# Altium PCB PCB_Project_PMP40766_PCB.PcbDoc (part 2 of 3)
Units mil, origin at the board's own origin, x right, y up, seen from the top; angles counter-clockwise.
Board outline 7480.31 x 3937.01 mil, 2 copper layers (Top Layer, Bottom Layer), stack 64.8 mil thick; 214 components, 118 nets, 518 pads, 70 vias.
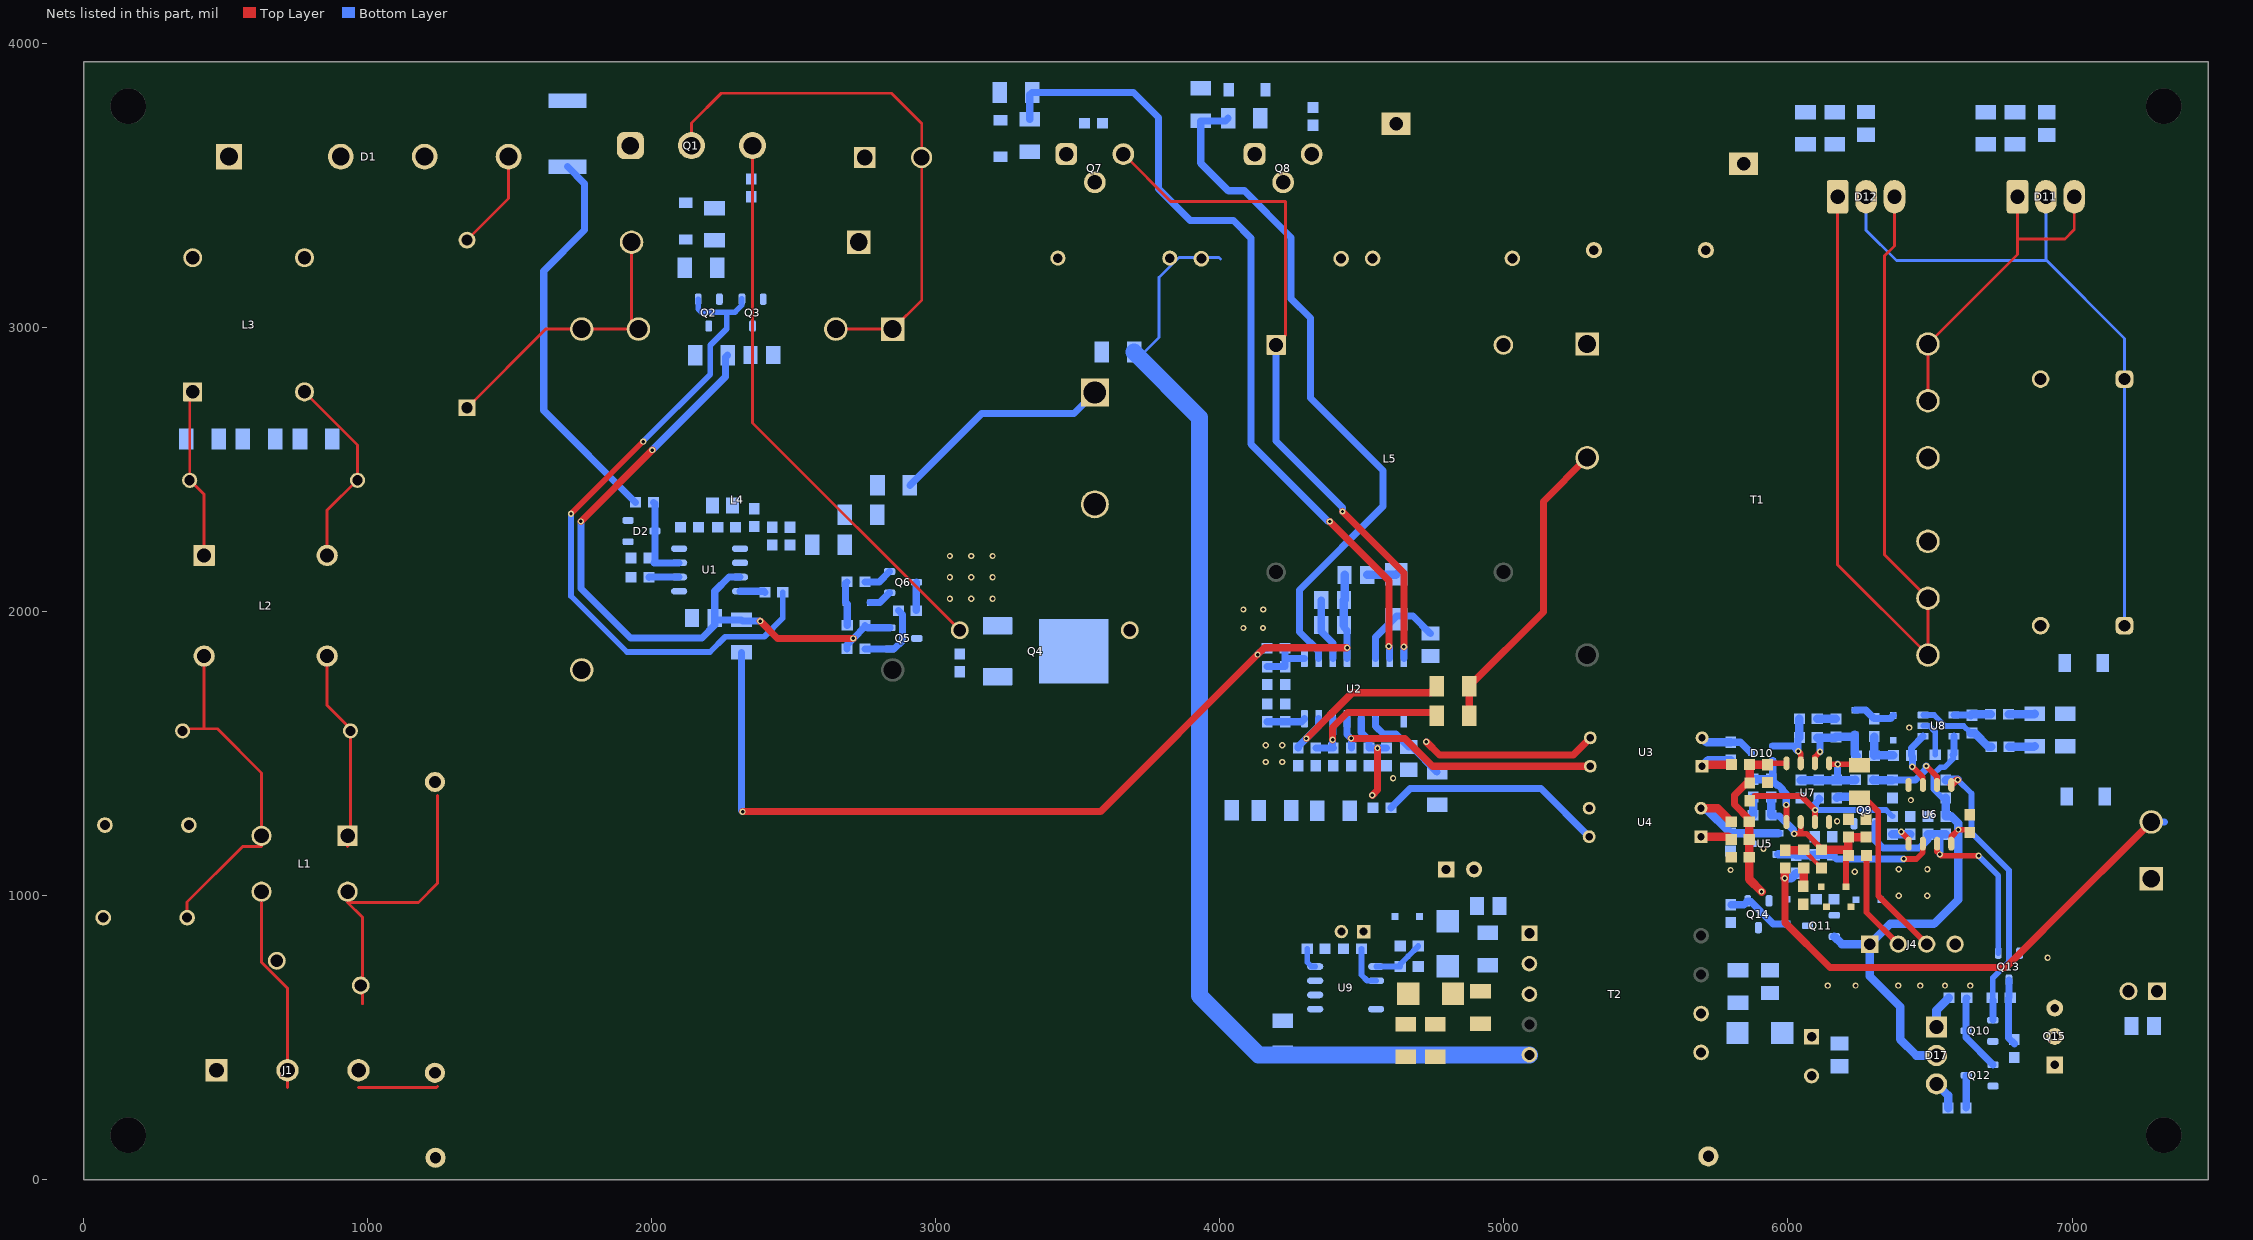
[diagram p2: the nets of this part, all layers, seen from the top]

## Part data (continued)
D13 D14 D15 D16: library part CMP-0028449-2, "Diode, Schottky, 30 V, 0.2 A, SOD-323", Manufacturer="Diodes Inc.", Value1=0.2A, Value2=1V
D17: library part CMP-0087778-1, "LED GRN/RED DIFF 5MM ROUND T/H", Color="Green, Red", Manufacturer="Marktech Optoelectronics"
D18: library part CMP-0085741-1, "Diode, Zener, 5.6 V, 300 mW, SOD-323", Manufacturer="ON Semiconductor", Power_W=300mW, Value1=0.3W
D19: library part CMP-0082069-2, "Diode, Switching, 75 V, 0.15 A, SOD-323", Manufacturer="Micro Commercial Components", Value1=0.15A, Value2=1V
D20 D22: library part CMP-0029024-2, "Diode, Ultrafast, 200 V, 1 A, SMA", Manufacturer="Diodes Inc.", Value1=1A, Value2=0.92V
D21: library part CMP-0076882-2, "Diode, Ultrafast, 1000 V, 1 A, SMA", Manufacturer="Diodes Inc.", Value1=1A, Value2=1.7V
D23: library part CMP-0085756-1, "Diode, Zener, 11 V, 300 mW, SOD-323", Manufacturer="ON Semiconductor", Power_W=300mW, Value1=0.3W
F1: library part CMP-0079917-2, "Fuse, 10 A, 250 VAC, TH", Irating_A=10A, Manufacturer=Littelfuse, PartNumber=0216008.MXEP, Supplier Part Number 1=F3603-ND
H1: library part 7106DG, Manufacturer=Aavid
H2: library part 7106DG, Manufacturer=Aavid, PartNumber=40mm*40mm
J1: library part CMP-0055483-1, "Terminal Block, 3x1, 6.35 mm, TH", Manufacturer="Phoenix Contact", Supplier Part Number 1=277-1270-ND
J2: library part CMP-0054770-2, "Receptacle, 5.08mm, 2x1, Brass, TH", Color=Green, Current_A=10A, Manufacturer="Wurth Elektronik", Supplier Part Number 1=732-2749-ND, Voltage_V=300V
J3: library part CMP-0055242-1, "Header(shrouded), 2.54mm, 2x1, Gold, TH", Color=Black, Current_A=3A, Manufacturer=Molex, Supplier Part Number 1=WM4800-ND, Voltage_V=250V
J4: library part CMP-0055331-1, "Header, 2.54mm, 4x1, Tin, TH", Color=Black, Current_A=4A, Manufacturer=Molex, Supplier Part Number 1=WM50016-04-ND, Voltage_V=250V
L1: library part CMP-0013095-2, "Coupled inductor, 8.5 A, 0.0055 ohm, TH", Manufacturer="Wurth Elektronik", Supplier Part Number 1=732-3246-ND
L2: library part CMP-0089807-1, "8.3mH @ 10kHz 2 Line Common Mode Choke Through Hole DCR 12mOhm", Manufacturer="Yaxing Development", Operating Temperature Range=to, Test Frequency=10kHz, Tolerance_%=30%
L3: library part CMP-0013082-2, "Coupled inductor, 7 mH, 7 A, 0.02 ohm, TH", Manufacturer="Wurth Elektronik", Supplier Part Number 1=732-5589-ND, ValueDisplayed=7mH
L4: library part "PFC Choke", "Transformer, 340 uH, TH", ValueDisplayed=340µH
L5: library part "LLC Inductor", "Transformer, 58uH, TH", ValueDisplayed=58µH
LOGO1: library part CMP-0074835-1, "IEC 61010-1 High Voltage Warning"
LOGO2: library part CMP-0074837-1, "IEC 61010-1 Hot Surface Warning"
Logo3: library part CMP-0074847-1, "FCC_disclaimer"
Logo4: library part CMP-0074769-1
Q1: library part CMP-0001178-3, "MOSFET, N-CH, 600 V, 37 A, TO-247", Alternate Manufacturer=None, Manufacturer="Infineon Technologies", Supplier Part Number 1=IPW60R080P7XKSA1-ND, Value2="51 nC"
Q2: library part CMP-0000461-2, "Transistor, NPN, 40 V, 0.6 A, SOT-23", Manufacturer="ON Semiconductor", Supplier Part Number 1=MMBT2222ALT1GOSCT-ND, Value1="0.6 A"
Q3: library part CMP-0000344-2, "Transistor, PNP, 60 V, 0.6 A, SOT-23", Manufacturer="ON Semiconductor", Supplier Part Number 1=MMBT2907ALT1GOSCT-ND, Value1="0.6 A"
Q4: library part CMP-0079238-2, "MOSFET, N-CH, 600 V, 18 A, DPAK", Alternate Manufacturer=None, Manufacturer="Infineon Technologies", Supplier Part Number 1=IPD60R180P7SAUMA1CT-ND, Value1="180m ohm", Value2="25 nC"
Q5: library part CMP-0000325-2, "Transistor, PNP, 40 V, 0.2 A, SOT-23", Manufacturer="ON Semiconductor", Supplier Part Number 1=MMBT3906LT1GOSCT-ND, Value1="0.2 A", Value2=300
Q6 Q11 Q14: library part CMP-0000419-2, "Transistor, NPN, 40 V, 0.2 A, SOT-23", Manufacturer="ON Semiconductor", Supplier Part Number 1=MMBT3904LT1GOSCT-ND, Value1="0.2 A", Value2=300
Q7 Q8: library part CMP-0079306-2, "MOSFET, N-CH, 600 V, 8 A, TO-220FP", Alternate Manufacturer=None, Manufacturer="Infineon Technologies", Value1="? ohm", Value2="28 nC"
Q9 Q10 Q12 Q13: library part CMP-0000769-1, "MOSFET, N-CH, 60 V, 0.17 A, SOT-23", Alternate Manufacturer=None, Manufacturer="Diodes Inc.", Supplier Part Number 1=2N7002-FDICT-ND, Value1=7, Value2="223 nC"
Q15: library part CMP-0000425-2, "Transistor, NPN, 40 V, 0.5 A, TO-92AP", Manufacturer="Micro Commercial Components", Supplier Part Number 1=2N4401-APCT-ND, Value1="0.5 A", Value2=300
R1 R2 R3: library part CMP-0018205-2, "RES, 330 k, 1%, 0.25 W, 1206", Manufacturer="Yageo America", Power_W=250mW, Supplier Part Number 1=311-330KFRCT-ND, TempCo="100 ppm/C", Tolerance_%=1%, Value2=0.25W, Value_Code=330k
R4 R18 R74: library part CMP-0018759-2, "RES, 0, 5%, 0.25 W, 1206", Manufacturer="Yageo America", Power_W=250mW, Supplier Part Number 1=311-0.0ERCT-ND, TempCo="200 ppm/C", Tolerance_%=5%, Value2=0.25W, Value_Code=0000, ValueDisplayed=0
R5: library part CMP-0022918-5, "RES, 220, 1%, 0.1 W, 0603", Manufacturer=Yageo, Power_W=100mW, Supplier Part Number 1=311-220HRCT-ND, TempCo="100 ppm/C", Tolerance_%=1%, Value2=0.1W, Value_Code=220R, ValueDisplayed=220
R6: library part CMP-0022913-5, "RES, 21.5 k, 1%, 0.1 W, 0603", Manufacturer=Yageo, Power_W=100mW, Supplier Part Number 1=311-21.5KHRCT-ND, TempCo="100 ppm/C", Tolerance_%=1%, Value2=0.1W, Value_Code=21k5, ValueDisplayed=21.5k
R7: library part CMP-0015773-2, "RES, 0.02, 1%, 2 W, 2512", Manufacturer="Stackpole Electronics Inc", Power_W=2W, Supplier Part Number 1=CSRN2512FK20L0CT-ND, TempCo="200 ppm/C", Tolerance_%=1%, Value_Code=R020, ValueDisplayed=0.02
R8 R20 R33 R34 R42 R44 R52 R84 R86: library part CMP-0022746-5, "RES, 10.0 k, 1%, 0.1 W, 0603", Manufacturer=Yageo, Power_W=100mW, Supplier Part Number 1=311-10.0KHRCT-ND, TempCo="100 ppm/C", Tolerance_%=1%, Value2=0.1W, Value_Code=10k0, ValueDisplayed=10.0k
R9 R12 R13: library part CMP-0018270-2, "RES, 3.30, 1%, 0.25 W, 1206", Manufacturer="Yageo America", Power_W=250mW, Supplier Part Number 1=311-3.30FRCT-ND, TempCo="200 ppm/C", Tolerance_%=1%, Value2=0.25W, Value_Code=3R30, ValueDisplayed=3.30
R10: library part CMP-0022761-5, "RES, 11.5 k, 1%, 0.1 W, 0603", Manufacturer=Yageo, Power_W=100mW, Supplier Part Number 1=311-11.5KHRCT-ND, TempCo="100 ppm/C", Tolerance_%=1%, Value2=0.1W, Value_Code=11k5, ValueDisplayed=11.5k
R11 R67 R70: library part CMP-0022751-4, "RES, 10.0, 1%, 0.1 W, 0603", Manufacturer=Yageo, Power_W=100mW, Supplier Part Number 1=311-10.0HRCT-ND, TempCo="100 ppm/C", Tolerance_%=1%, Value2=0.1W, Value_Code=10R0, ValueDisplayed=10.0
R14 R15 R16: library part CMP-0018027-2, "RES, 1.00 M, 1%, 0.25 W, 1206", Manufacturer="Yageo America", Power_W=250mW, Supplier Part Number 1=311-1.00MFRCT-ND, TempCo="100 ppm/C", Tolerance_%=1%, Value2=0.25W, Value_Code=1M00, ValueDisplayed=1.00M
R17: library part CMP-0023073-5, "RES, 39.0 k, 1%, 0.1 W, 0603", Manufacturer=Yageo, Power_W=100mW, Supplier Part Number 1=311-39.0KHRCT-ND, TempCo="100 ppm/C", Tolerance_%=1%, Value2=0.1W, Value_Code=39k0, ValueDisplayed=39.0k
R19 R21 R22 R64: library part CMP-0022735-5, "RES, 100 k, 1%, 0.1 W, 0603", Manufacturer=Yageo, Power_W=100mW, Supplier Part Number 1=311-100KHRCT-ND, TempCo="100 ppm/C", Tolerance_%=1%, Value2=0.1W, Value_Code=100k
R23: library part CMP-0022770-4, "RES, 121 k, 1%, 0.1 W, 0603", Manufacturer=Yageo, Power_W=100mW, Supplier Part Number 1=311-121KHRCT-ND, TempCo="100 ppm/C", Tolerance_%=1%, Value2=0.1W, Value_Code=121k
R24 R25 R26: library part CMP-0017039-3, "RES, 4.99 M, 1%, 0.25 W, AEC-Q200 Grade 0, 1206", Manufacturer=Vishay-Dale, Power_W=250mW, Supplier Part Number 1=541-4.99MFCT-ND, TempCo="100 ppm/C", Tolerance_%=1%, Value2=0.25W, Value_Code=4M99, ValueDisplayed=4.99M
R27: library part CMP-0023150-5, "RES, 4.53 k, 1%, 0.1 W, 0603", Manufacturer=Yageo, Power_W=100mW, Supplier Part Number 1=311-4.53KHRCT-ND, TempCo="100 ppm/C", Tolerance_%=1%, Value2=0.1W, Value_Code=4k53, ValueDisplayed=4.53k
R28 R29: library part CMP-0018059-2, "RES, 1.00, 1%, 0.25 W, 1206", Manufacturer="Yageo America", Power_W=250mW, Supplier Part Number 1=311-1.00FRCT-ND, TempCo="200 ppm/C", Tolerance_%=1%, Value2=0.25W, Value_Code=1R00, ValueDisplayed=1.00
R30 R31 R48 R49 R50 R51 R75 R81: library part CMP-0017851-2, "RES, 10.0, 1%, 0.25 W, 1206", Manufacturer="Yageo America", Power_W=250mW, Supplier Part Number 1=311-10.0FRCT-ND, TempCo="200 ppm/C", Tolerance_%=1%, Value2=0.25W, Value_Code=10R0, ValueDisplayed=10.0
R32: library part CMP-0021901-2, "RES, 2.20, 1%, 0.125 W, 0805", Manufacturer="Yageo America", Power_W=125mW, Supplier Part Number 1=311-2.20CRCT-ND, TempCo="200 ppm/C", Tolerance_%=1%, Value2=0.125W, Value_Code=2R20, ValueDisplayed=2.20
R35 R79: library part CMP-0023292-5, "RES, 82.0 k, 1%, 0.1 W, 0603", Manufacturer=Yageo, Power_W=100mW, Supplier Part Number 1=311-82.0KHRCT-ND, TempCo="100 ppm/C", Tolerance_%=1%, Value2=0.1W, Value_Code=82k0, ValueDisplayed=82.0k
R36: library part CMP-0023167-5, "RES, 51.0 k, 1%, 0.1 W, 0603", Manufacturer=Yageo, Power_W=100mW, Supplier Part Number 1=311-51.0KHRCT-ND, TempCo="100 ppm/C", Tolerance_%=1%, Value2=0.1W, Value_Code=51k0, ValueDisplayed=51.0k
R37: library part CMP-0022901-4, "RES, 200 k, 1%, 0.1 W, 0603", Manufacturer=Yageo, Power_W=100mW, Supplier Part Number 1=311-200KHRCT-ND, TempCo="100 ppm/C", Tolerance_%=1%, Value2=0.1W, Value_Code=200k
R38: library part CMP-0022845-5, "RES, 180, 1%, 0.1 W, 0603", Manufacturer=Yageo, Power_W=100mW, Supplier Part Number 1=311-180HRCT-ND, TempCo="100 ppm/C", Tolerance_%=1%, Value2=0.1W, Value_Code=180R, ValueDisplayed=180
R39 R41 R56 R82: library part CMP-0023091-5, "RES, 3.00 k, 1%, 0.1 W, 0603", Manufacturer=Yageo, Power_W=100mW, Supplier Part Number 1=311-3.00KHRCT-ND, TempCo="100 ppm/C", Tolerance_%=1%, Value2=0.1W, Value_Code=3k00, ValueDisplayed=3.00k
R40: library part CMP-0023246-5, "RES, 6.04 k, 1%, 0.1 W, 0603", Manufacturer=Yageo, Power_W=100mW, Supplier Part Number 1=311-6.04KHRCT-ND, TempCo="100 ppm/C", Tolerance_%=1%, Value2=0.1W, Value_Code=6k04, ValueDisplayed=6.04k
R43: library part CMP-0023014-4, "RES, 301 k, 1%, 0.1 W, 0603", Manufacturer=Yageo, Power_W=100mW, Supplier Part Number 1=311-301KHRCT-ND, TempCo="100 ppm/C", Tolerance_%=1%, Value2=0.1W, Value_Code=301k
R45 R47 R58: library part CMP-0023198-5, "RES, 5.10 k, 1%, 0.1 W, 0603", Manufacturer=Yageo, Power_W=100mW, Supplier Part Number 1=311-5.10KHRCT-ND, TempCo="100 ppm/C", Tolerance_%=1%, Value2=0.1W, Value_Code=5k10, ValueDisplayed=5.10k
R46: library part CMP-0023279-5, "RES, 7.50 k, 1%, 0.1 W, 0603", Manufacturer=Yageo, Power_W=100mW, Supplier Part Number 1=311-7.50KHRCT-ND, TempCo="100 ppm/C", Tolerance_%=1%, Value2=0.1W, Value_Code=7k50, ValueDisplayed=7.50k
R53: library part CMP-0023239-5, "RES, 68.0 k, 1%, 0.1 W, 0603", Manufacturer=Yageo, Power_W=100mW, Supplier Part Number 1=311-68.0KHRCT-ND, TempCo="100 ppm/C", Tolerance_%=1%, Value2=0.1W, Value_Code=68k0, ValueDisplayed=68.0k
R54 R57: library part CMP-0022991-5, "RES, 2.40 k, 1%, 0.1 W, 0603", Manufacturer=Yageo, Power_W=100mW, Supplier Part Number 1=311-2.40KHRCT-ND, TempCo="100 ppm/C", Tolerance_%=1%, Value2=0.1W, Value_Code=2k40, ValueDisplayed=2.40k
R55: library part CMP-0022849-5, "RES, 187, 1%, 0.1 W, 0603", Manufacturer=Yageo, Power_W=100mW, Supplier Part Number 1=311-187HRCT-ND, TempCo="100 ppm/C", Tolerance_%=1%, Value2=0.1W, Value_Code=187R, ValueDisplayed=187
R59: library part CMP-0023141-5, "RES, 499, 1%, 0.1 W, 0603", Manufacturer=Yageo, Power_W=100mW, Supplier Part Number 1=311-499HRCT-ND, TempCo="100 ppm/C", Tolerance_%=1%, Value2=0.1W, Value_Code=499R, ValueDisplayed=499
R60: library part CMP-0023000-5, "RES, 2.00 k, 1%, 0.1 W, 0603", Manufacturer=Yageo, Power_W=100mW, Supplier Part Number 1=311-2.00KHRCT-ND, TempCo="100 ppm/C", Tolerance_%=1%, Value2=0.1W, Value_Code=2k00, ValueDisplayed=2.00k
R61 R63: library part CMP-0022908-4, "RES, 20.0, 1%, 0.1 W, 0603", Manufacturer=Yageo, Power_W=100mW, Supplier Part Number 1=311-20.0HRCT-ND, TempCo="100 ppm/C", Tolerance_%=1%, Value2=0.1W, Value_Code=20R0, ValueDisplayed=20.0
R62: library part CMP-0022031-4, "RES, 12.4 k, 1%, 0.1 W, AEC-Q200 Grade 0, 0603", Manufacturer=Vishay-Dale, Power_W=100mW, Supplier Part Number 1=541-12.4KHCT-ND, TempCo="100 ppm/C", Tolerance_%=1%, Value2=0.1W, Value_Code=12k4, ValueDisplayed=12.4k
R65: library part CMP-0023197-5, "RES, 5.11 k, 1%, 0.1 W, 0603", Manufacturer=Yageo, Power_W=100mW, Supplier Part Number 1=311-5.11KHRCT-ND, TempCo="100 ppm/C", Tolerance_%=1%, Value2=0.1W, Value_Code=5k11, ValueDisplayed=5.11k
R66 R83: library part CMP-0022895-5, "RES, 1.00 k, 1%, 0.1 W, 0603", Manufacturer=Yageo, Power_W=100mW, Supplier Part Number 1=311-1.00KHRCT-ND, TempCo="100 ppm/C", Tolerance_%=1%, Value2=0.1W, Value_Code=1k00, ValueDisplayed=1.00k
R68 R69: library part CMP-0017256-2, "RES, 0.01, 1%, 0.5 W, 1206", Manufacturer="Stackpole Electronics Inc", Power_W=500mW, Supplier Part Number 1=CSR1206FK10L0CT-ND, TempCo="100 ppm/C", Tolerance_%=1%, Value2=0.5W, Value_Code=R010, ValueDisplayed=0.01
R71 R72: library part CMP-0023163-5, "RES, 510, 1%, 0.1 W, 0603", Manufacturer=Yageo, Power_W=100mW, Supplier Part Number 1=311-510HRCT-ND, TempCo="100 ppm/C", Tolerance_%=1%, Value2=0.1W, Value_Code=510R, ValueDisplayed=510
R73: library part CMP-0023086-5, "RES, 3.60 k, 1%, 0.1 W, 0603", Manufacturer=Yageo, Power_W=100mW, Supplier Part Number 1=311-3.60KHRCT-ND, TempCo="100 ppm/C", Tolerance_%=1%, Value2=0.1W, Value_Code=3k60, ValueDisplayed=3.60k
R76: library part CMP-0018060-2, "RES, 200 k, 1%, 0.25 W, 1206", Manufacturer="Yageo America", Power_W=250mW, Supplier Part Number 1=311-200KFRCT-ND, TempCo="100 ppm/C", Tolerance_%=1%, Value2=0.25W, Value_Code=200k
R77: library part CMP-0018061-2, "RES, 200, 1%, 0.25 W, 1206", Manufacturer="Yageo America", Power_W=250mW, Supplier Part Number 1=311-200FRCT-ND, TempCo="100 ppm/C", Tolerance_%=1%, Value2=0.25W, Value_Code=200R, ValueDisplayed=200
R78: library part CMP-0022892-5, "RES, 1.80 k, 1%, 0.1 W, 0603", Manufacturer=Yageo, Power_W=100mW, Supplier Part Number 1=311-1.80KHRCT-ND, TempCo="100 ppm/C", Tolerance_%=1%, Value2=0.1W, Value_Code=1k80, ValueDisplayed=1.80k
R80: library part CMP-0023020-5, "RES, 30.0 k, 1%, 0.1 W, 0603", Manufacturer=Yageo, Power_W=100mW, Supplier Part Number 1=311-30.0KHRCT-ND, TempCo="100 ppm/C", Tolerance_%=1%, Value2=0.1W, Value_Code=30k0, ValueDisplayed=30.0k
R85: library part CMP-0017847-2, "RES, 10.0 k, 1%, 0.25 W, 1206", Manufacturer="Yageo America", Power_W=250mW, Supplier Part Number 1=311-10.0KFRCT-ND, TempCo="100 ppm/C", Tolerance_%=1%, Value2=0.25W, Value_Code=10k0, ValueDisplayed=10.0k
R87: library part CMP-0022808-4, "RES, 150 k, 1%, 0.1 W, 0603", Manufacturer=Yageo, Power_W=100mW, Supplier Part Number 1=311-150KHRCT-ND, TempCo="100 ppm/C", Tolerance_%=1%, Value2=0.1W, Value_Code=150k
RF1: library part CMP-0014288-1, "RES, 47, 10%, 2 W, Axial resistor", Manufacturer="TT Electronics/IRC", Power_W=2W, Supplier Part Number 1=985-1022-1-ND, TempCo="100 ppm/C", Tolerance_%=10%, Value_Code=47R0, ValueDisplayed=47
RV1: library part CMP-0002100-2, "Varistor 275V RMS 10MM Radial, TH", Manufacturer=TDK, Supplier Part Number 1=495-1433-ND
T1: library part "LLC Transformer", "Transformer, 200 uH, PQ3230", ValueDisplayed=200µH
T2: library part EE16, "Transformer, 1.8mH, TH", Manufacturer="TE Connectivity", ValueDisplayed=1800µH
U1: library part CMP-0074100-1, "8-PIN CONTINUOUS CONDUCTION MODE (CCM) PFC CONTROLLER, D0008A (SOIC-8)", Alternate Manufacturer="Texas Instruments", Alternate PartNumber=UCC28180D
U2: library part CMP-0088180-2, "Switching Controllers LLC resonant controller with ultra-low power and ultra-quiet standby operation 14-SOIC -40 to 125", Manufacturer="Texas Instruments", Operating Temperature Range="-40°C to +125°C"
U3 U4: library part CMP-0006173-3, "Optocoupler, 5 kV, 80-160% CTR, TH", Manufacturer="Fairchild Semiconductor", Supplier Part Number 1=FOD817A-ND, Voltage_Isolation_Vrms=5kV
U5: library part CMP-0084729-1, "Programmable Shunt Regulator with Optimized Reference Current, DBZ0003A (SOT-23-3)", Alternate Manufacturer="Texas Instruments"
U6: library part CMP-0075718-1, "GENERAL-PURPOSE LOW-VOLTAGE COMPARATORS, D0008A (SOIC-8)", Alternate Manufacturer="Texas Instruments"
U7: library part CMP-0043697-1, "Dual Operational Amplifier with Internal Reference, 3 to 32 V, -40 to 105 degC, 8-pin SOIC (D8), Green (RoHS & no Sb/Br)", Manufacturer="Texas Instruments", Rating=Catalog, Total Supply Voltage(Max)(+5V is 5, +/-5V is 10)=32, Total Supply Voltage(Min)(+5V is 5, +/-5V is 10)=3
U8: library part CMP-0013064-2, "Low- and High-Side Measurement, Multichannel, Voltage Output, Current-Sense Amplifier, DBV0005A (SOT-5)", Alternate Manufacturer="Texas Instruments"
U9: library part CMP-0067241-2, "700V Flyback Switcher with Constant-Voltage Constant-Current and Primary-side Control, D0007A (SOIC-7)", Alternate Manufacturer="Texas Instruments", Alternate PartNumber=UCC28910D

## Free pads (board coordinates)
  round 125.98 hole 125.98: 1(157.48,157.48) 1(157.48,3779.53) 1(7322.83,157.48) 1(7322.83,3779.53)
  round 70.87 hole 39.37: 1(1239,78) 1(5720,83)

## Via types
v1: diameter 22, hole 12, Top Layer to Bottom Layer, tented both sides, 70 vias

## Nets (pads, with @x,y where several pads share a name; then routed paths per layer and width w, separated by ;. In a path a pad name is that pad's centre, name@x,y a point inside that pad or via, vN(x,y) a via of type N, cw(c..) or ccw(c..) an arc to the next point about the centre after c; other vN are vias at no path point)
5V: C43.1 C47.1 D17.2 J4.1 Q11.2 R47.2 R66.1 U6.8 U8.5 | length 1818.9
  Top Layer w20: U6.8@6575,1183.65 6575,1208.26 v1(6600,1233.26) 6629.5,1233.26 C43.1@6640,1222.76
  Bottom Layer w20: R66.1@6556,1344.76 6543.5,1344.76 6511,1377.26 6511,1427.26 6536,1452.26 6551,1452.26 6581.5,1482.76 C47.1@6581.5,1496.26
  Bottom Layer w25: C47.1@6581.5,1496.26 6584.13,1498.9 U8.5@6584.13,1561.86
  Bottom Layer w30: Q11.2@6163.24,856.86 6190.1,830 J4.1@6288.44,830 ; D17.2@6523,438 6452,438 6395,495 6395,610 6288.44,716.56 J4.1@6288.44,830 ; R66.1@6556,1344.76 6555,1343.76 R47.2@6555,1279.76 6575.5,1279.76 6600,1255.26 v1(6600,1233.26) 6600,987 6514,901 6359.44,901 J4.1@6288.44,830
10V_A: C35.1 C57.1 Q11.3 Q14.2 R39.2 R40.2 R42.2 R56.1 R73.1 U7.8 | length 647.8
  Top Layer w20: C35.1@5928,1461.76 5932.85,1466.61 U7.8@5995,1466.61
  Top Layer w25: R42.2@5863.5,1260.26 5863.5,1269.76 5812,1321.26 5812,1354.26 5854,1396.26 R56.1@5864.5,1396.26
  Top Layer w30: R42.2@5863.5,1260.26 R39.2@5863.5,1198.26 C57.1@5863.5,1136.26 5863.5,1058.5 v1(5907,1015) ; R56.1@5864.5,1396.26 R56.1@5866,1397.76 5866,1460.76 R40.2@5865,1461.76 ; R40.2@5864.5,1462.26 R40.2@5865,1461.76 ; C35.1@5928,1461.76 R40.2@5865,1461.76
12VS: C53.1 C54.1 C55.1 C56.1 D22.1 J3.1 Q14.3 R82.1
BLK: C16.1 R23.2 R26.1 R36.2 U2.4 | length 349.4
  Top Layer w25: v1(4537,1354.26) 4555,1372.26 v1(4555,1520.26)
  Bottom Layer w25: U2.4@4498,1623.47 4498,1575.26 4525,1548.26 C16.1@4525,1520.76 R23.2@4587,1520.76
EARTH: CY1.1 CY2.2 J1.1 pad.1@1239,78
FAN_OFF: Q9.1 Q13.1 R47.1 R52.2 U6.7 | length 978.4
  Top Layer w20: U6.7@6525,1183.65 6525,1156 v1(6535,1146) 6539.83,1141.17 6670.83,1141.17 v1(6671,1141)
  Bottom Layer w20: v1(6671,1141) 6740.6,1071.4 Q13.1@6740.6,798.24
  Bottom Layer w25: Q9.1@6307.4,1254.02 6307.4,1195.86 6335,1168.26 6464,1168.26 6493,1197.26 R52.2@6493,1216.76 ; 6523,1216.76 6533,1206.76 6530,1203.76 6535,1198.76 v1(6535,1146)
  Bottom Layer w30: R52.2@6493,1216.76 6523,1216.76 R47.1@6555,1216.76
FAN_ON: Q10.1 R66.2 R83.2 U6.1 | length 1016.6
  Top Layer w25: U6.1@6575,1390.35 6592.91,1408.26 v1(6598,1408.26)
  Bottom Layer w20: v1(6598,1408.26) 6646,1360.26 6646,1222 6778,1090 6778,768 6721.24,711.24 R83.2@6721.24,633.26
  Bottom Layer w25: Q10.1@6721.24,562.4 R83.2@6721.24,633.26
  Bottom Layer w30: R66.2@6556,1407.76 6556.5,1408.26 v1(6598,1408.26)
FB: C20.1 U2.5 U3.4 | length 991.7
  Top Layer w25: v1(4462,1554.26) 4651,1554.26 4749,1456.26 U3.4@5304.15,1456.26
  Bottom Layer w25: U2.5@4448,1623.47 4448,1568.26 v1(4462,1554.26) 4463,1553.26 C20.1@4463,1520.76
HB: C21.2 D9.1 U2.14 | length 323.6
  Bottom Layer w25: U2.14@4548,1836.07 4548,1910.26 4623,1985.26 4679.74,1985.26 C21.2@4741,1924
HO: R28.1 R30.1 U2.15 | length 2913
  Top Layer w25: v1(4387,2318) 4595,2110 v1(4595,1878.26)
  Bottom Layer w25: R30.1@3331,3733.35 3331,3820.17 R28.1@3339.09,3828.26 3696,3828.26 3784,3740.26 3784,3489.26 3896,3377.26 4048,3377.26 4110,3315.26 4110,2590 4382,2318 v1(4387,2318) ; v1(4595,1878.26) 4598,1875.26 U2.15@4598,1836.07
HS: C21.1 L5.1 Q7.3 Q8.2 R33.1 U2.16 | length 2448
  Top Layer w10: Q7.3@3660.39,3611.26 3827.39,3444.26 4231,3444.26 4231,2972.26 L5.1@4198,2939.26
  Top Layer w25: v1(4432,2353) 4648,2137 v1(4648,1877)
  Bottom Layer w25: L5.1@4198,2939.26 4198,2601 4432,2367 v1(4432,2353) ; U2.16@4648,1836.07 v1(4648,1877)
IREF: C36.2 R55.2 R57.1 R58.2 R85.1 U7.5 | length 358.4
  Top Layer w20: U7.5@6145,1466.61 6148.35,1463.26 v1(6175,1463.26) 6248.33,1463.26 R85.1@6252,1459.59
  Bottom Layer w25: R55.2@6172,1407.76 6175,1410.76 v1(6175,1463.26)
  Bottom Layer w30: C36.2@6046,1407.76 R57.1@6109,1407.76 R55.2@6172,1407.76 6237,1407.76 R58.2@6237.5,1408.26
ISNS: C26.2 C28.1 R38.2 U2.6 | length 605.6
  Top Layer w25: v1(4397,1549.24) 4397,1592.26 4450,1645.26 4752.91,1645.26 C26.2@4763.91,1634.26
  Bottom Layer w10: U2.6@4398,1623.47 U2.6@4400,1621.47
  Bottom Layer w25: R38.2@4338,1520.76 C28.1@4400,1520.76 4397,1523.76 v1(4397,1549.24) 4397,1569.26 4398,1570.26 U2.6@4398,1623.47
"L Wire": F1.2 J1.3 | length 279.7
  Top Layer w10: 968,325.26 1241.81,325.26 1246,329.45
LL: C19.1 R35.2 R37.2 U2.9 | length 259.2
  Bottom Layer w10: R35.2@4167,1806.76 C19.1@4230,1806.76
  Bottom Layer w25: R35.2@4167,1806.76 C19.1@4230,1806.76 4230,1837.26 ; R37.2@4229.5,1871.26 4230,1870.76 4230,1837.26 ; U2.9@4298,1836.07 4231.19,1836.07 4230,1837.26
LO: R29.1 R31.1 U2.10 | length 2441.3
  Bottom Layer w25: R31.1@4028.91,3737.26 4019.83,3728.17 R29.1@3933,3728.17 3933,3579.26 4030,3482.26 4086.74,3482.26 4251,3318 4251,3102 4319,3034 4319,2753 4575,2497 4575,2371.26 4280,2076.26 4280,1929.26 4348,1861.26 U2.10@4348,1836.07
"N Wire": J1.2 L1.3 RV1.2 | length 689.5
  Top Layer w10: 626.43,976.83 626.43,766.5 686.36,706.57 718,674.93 718,325.26
NetC1_1: C1.1 CY2.1 L1.1 L2.3 | length 709.1
  Top Layer w10: L2.3@857.54,1844.09 857.54,1671 940.28,1588.26 940.28,1184.39 929.57,1173.69
NetC1_2: C1.2 CY1.2 L1.4 L2.4 | length 1254.6
  Top Layer w10: C1.2@349.72,1588.26 422,1588.26 ; CY1.2@364.64,923.26 364.64,977.9 560.43,1173.69 626.43,1173.69 626.43,1432.83 471,1588.26 422,1588.26 ; L2.4@424.46,1844.09 424.46,1590.72 422,1588.26
NetC2_1: C2.1 L2.1 L3.1 R3.1 | length 600.9
  Top Layer w10: L3.1@384.15,2774.04 373.72,2763.61 373.72,2464.26 424.46,2413.52 L2.1@424.46,2198.43
NetC2_2: C2.2 L2.2 L3.2 R1.2 | length 697
  Top Layer w10: L3.2@777.85,2774.04 964.28,2587.61 964.28,2464.26 857.54,2357.52 L2.2@857.54,2198.43
NetC4_1: C4.1 U1.2 | length 106.6
  Bottom Layer w25: C4.1@1990.5,2121.26 1991.5,2122.26 U1.2@2096.72,2122.26
NetC5_1: C5.1 D1.1 D3.2 L4.5 L4.6 | length 1034.6
  Top Layer w10: C5.1@1350,2717.98 1627.28,2995.26 L4.6@1753.56,2995.26 L4.5@1953.56,2995.26 1929,3019.82 D3.2@1929,3301.26
NetC5_2: C5.2 D1.4 R5.2 R7.1 | length 1754.6
  Top Layer w10: C5.2@1350,3308.54 1496.13,3454.66 D1.4@1496.13,3602.26
  Bottom Layer w25: R7.1@1704,3567.12 1764,3507.12 1764,3344.26 1620,3200.26 1620,2708.76 R5.2@1943.5,2385.26
NetC6_1: C6.1 D2.3 R5.1 U1.3 | length 305.7
  Bottom Layer w25: R5.1@2006.5,2385.26 2011.24,2380.51 D2.3@2011.24,2284.26 2011.24,2176.01 2007.5,2172.26 U1.3@2096.72,2172.26
NetC7_1: C7.1 R10.1
NetC8_1: C8.1 R10.2 U1.5
NetC9_1: C9.1 R16.1 R17.2 U1.6
NetC11_1: C11.1 D3.1 D5.1 R14.2 R18.1 | length 786.3
  Bottom Layer w25: R14.2@2909.09,2445.26 3162.09,2698.26 3486.15,2698.26 C11.1@3560,2772.11
NetC11_2: C11.2 Q4.2 RF1.1
NetC12_1: C12.1 D6.1 R19.1 | length 157.4
  Bottom Layer w25: C12.1@2687.5,2105.26 2682.69,2100.45 D6.1@2682.69,2032.26 2688.5,2026.45 R19.1@2688.5,1952.26
NetC18_1: C18.1 R27.2 U2.8 | length 135.5
  Bottom Layer w25: C18.1@4166.93,1612.76 R27.2@4230,1612.76 4287.29,1612.76 U2.8@4298,1623.47
NetC22_2: C22.2 C23.1 C24.1 C26.1 T1.3 | length 1080.3
  Top Layer w25: C26.1@4878.09,1634.26 C24.1@4878.09,1738.26 5139,1999.17 5139,2388.7 T1.3@5293,2542.7
NetC27_1: C27.1 R42.1 U4.2 U5.1 | length 434.2
  Top Layer w30: U4.2@5693.85,1308.26 5752.5,1308.26 R42.1@5800.5,1260.26
  Bottom Layer w30: U4.2@5693.85,1308.26 5710.5,1308.26 C27.1@5798,1220.76 5798.09,1220.66 U5.1@5965.24,1220.66
NetC29_1: C29.1 R43.1 R44.2 U5.2 U6.6 | length 558.2
  Top Layer w20: v1(6408,1130) 6452,1130 6475,1153 U6.6@6475,1183.65
  Bottom Layer w25: C29.1@6156,1144.76 6170.76,1130 v1(6408,1130)
  Bottom Layer w30: U5.2@5965.24,1145.86 6025.9,1145.86 R43.1@6029,1142.76 6091.99,1142.76 R44.2@6094,1144.76 C29.1@6156,1144.76
NetC31_1: C31.1 C34.2 D10.2 U7.1 | length 307.7
  Top Layer w20: v1(5994,1320.26) 5994,1314.26 5995,1313.26 U7.1@5995,1259.91
  Bottom Layer w25: D10.2@5946.4,1476.67 5946.4,1413.17 5942.5,1409.26 5963.93,1387.82 5968.14,1387.82 5980.07,1375.89 5980.07,1371.68 5994,1357.76 v1(5994,1320.26)
  Bottom Layer w30: C31.1@5878,1410.76 C34.2@5941,1410.76 C34.2@5942.5,1409.26
NetC31_2: C31.2 R53.2 | length 63.7
  Bottom Layer w30: R53.2@5877.5,1284.26 5878,1284.76 C31.2@5878,1347.76
NetC32_1: C32.1 C33.2 D10.1 U7.7 | length 259.5
  Top Layer w20: v1(6036,1509.26) 6045,1500.26 U7.7@6045,1466.61
  Bottom Layer w25: D10.1@5946.4,1527.85 6017.41,1527.85 v1(6036,1509.26) 6036,1552.76 C33.2@6040.5,1557.26
  Bottom Layer w30: C33.2@6040.5,1557.26 C32.1@6040.5,1623.26
NetC32_2: C32.2 R54.1 | length 65.7
  Bottom Layer w30: C32.2@6103.5,1623.26 6104,1622.76 R54.1@6169,1622.76
NetC33_1: C33.1 D13.1 R54.2 R60.1 U7.6 | length 314.5
  Top Layer w20: U7.6@6095,1466.61 6095,1489.26 v1(6113,1507.26)
  Bottom Layer w25: C33.1@6103.5,1557.26 6113,1547.76 v1(6113,1507.26)
  Bottom Layer w30: C33.1@6103.5,1557.26 6166.5,1557.26 R54.2@6169,1559.76 6228.81,1559.76 D13.1@6236,1566.95 6236,1498.76 R60.1@6241.5,1493.26
NetC37_2: C37.2 R48.2 R49.2
NetC38_2: C38.2 R50.2 R51.2
NetC40_1: C40.1 R60.2 R61.2 | length 135.1
  Bottom Layer w30: C40.1@6304,1560.76 6304.5,1560.27 R60.2@6304.5,1493.26 6305.5,1494.26 R61.2@6371.5,1494.26
NetC40_2: C40.2 D13.2 D15.1 | length 151.8
  Bottom Layer w25: D13.2@6236,1653.57 6274.19,1653.57 C40.2@6304,1623.76 6360.19,1623.76 D15.1@6371,1634.57
NetC42_1: C42.1 R87.1 | length 71.3
  Top Layer w30: C42.1@6052,1033.5 C42.1@6055.5,1037 ; C42.1@6054,1033.5 6055.5,1035 C42.1@6055.5,1037 ; R87.1@6055.5,1099.26 R87.1@6055.5,1098 C42.1@6055.5,1037
NetC42_2: C42.2 D14.1 D16.2
NetC45_1: C45.1 R67.1 U8.4 | length 131.2
  Bottom Layer w25: U8.4@6584.13,1636.66 6643.09,1636.66 C45.1@6644,1635.76
  Bottom Layer w30: C45.1@6644,1635.76 6647.5,1639.26 R67.1@6713.5,1639.26
NetC45_2: C45.2 R70.1 U8.3 | length 286.2
  Bottom Layer w20: U8.3@6475.87,1636.66 6514.6,1636.66 6553.06,1598.2 6618.57,1598.2 C45.2@6644,1572.76
  Bottom Layer w30: C45.2@6644,1572.76 6657.5,1572.76 6706,1524.26 R70.1@6715.5,1524.26
NetC46_2: C46.2 J2.1 R68.2 R69.2 R70.2 | length 91.7
  Bottom Layer w30: R70.2@6778.5,1524.26 6866.09,1524.26 R68.2@6869,1527.17
NetC48_1: C48.1 C50.1 D19.1 U9.6 | length 152.8
  Bottom Layer w20: C50.1@4498.5,814.26 4498.5,721.76 4519,701.26 U9.6@4550.28,701.26
NetC49_1: C49.1 C51.2 D19.2 D20.1 R74.2
NetC51_1: C51.1 R75.1
NetC52_2: C52.2 D21.1 R76.1
NetC53_2: C53.2 R81.2
NetC56_2: C56.2 J3.2 Q15.3
NetD1_2: D1.2 L3.4
NetD1_3: D1.3 L3.3
NetD4_1: D4.1 R12.2
NetD4_2: D4.2 Q1.1 R8.2 R9.2
NetD5_2: D5.2 L4.1 L4.2 Q1.2 | length 1943.3
  Top Layer w10: Q1.2@2140,3641.26 2140,3720.26 2245,3825.26 2844,3825.26 2951,3718.26 2951,3599.26 2951,3097.82 L4.1@2848.44,2995.26 L4.2@2648.44,2995.26
NetD6_2: D6.2 Q6.1 | length 82.8
  Bottom Layer w25: D6.2@2769.31,2032.26 2803.16,2032.26 Q6.1@2837.76,2066.86
NetD7_1: D7.1 R28.2
NetD7_2: D7.2 Q7.1 R30.2 R33.2
NetD8_1: D8.1 R29.2
NetD8_2: D8.2 Q8.1 R31.2 R34.2
NetD9_2: D9.2 R32.2 | length 102.7
  Bottom Layer w30: R32.2@4519,2130 4619.26,2130 D9.2@4621,2131.74
NetD10_3: D10.3 R41.2 U3.2 | length 196.1
  Bottom Layer w25: R41.2@5799,1540.76 5833.1,1540.76 D10.3@5871.6,1502.26
  Bottom Layer w30: U3.2@5697.85,1556.26 5713.35,1540.76 R41.2@5799,1540.76
NetD11_1: D11.1 D11.3 R48.1 R49.1 T1.11 T1.12 | length 1174.7
  Top Layer w10: T1.11@6493,2742.7 T1.12@6493,2942.7 6808,3257.7 6808,3312.26 ; D11.1@6808,3459.26 6808,3312.26 ; D11.3@7008,3459.26 7008,3345.26 6975,3312.26 6808,3312.26
NetD12_1: D12.1 D12.3 R50.1 R51.1 T1.7 T1.8 | length 3436.5
  Top Layer w10: D12.1@6175,3461.26 6175,2165.82 T1.7@6493,1847.82 T1.8@6493,2047.82 6340,2200.82 6340,3253.26 6375,3288.26 D12.3@6375,3461.26
NetD17_1: D17.1 R71.2 | length 121
  Bottom Layer w30: D17.1@6523,538 6523,597.5 R71.2@6566.5,641
NetD17_3: D17.3 R72.2 | length 101.8
  Bottom Layer w30: D17.3@6523,338 6563.5,297.5 R72.2@6563.5,253
NetD18_1: D18.1 Q11.1 R73.2
NetD20_2: D20.2 R75.2 R79.2 T2.2
NetD21_2: D21.2 R77.2
NetD22_2: D22.2 R81.1 T2.7
NetD23_1: D23.1 Q14.1 R82.2 | length 238.5
  Bottom Layer w25: R82.2@5799,968.76 5844.85,968.76 Q14.1@5858.6,982.5 5866.76,982.5 5948.31,900.95 D23.1@5998,900.95
NetF1_1: F1.1 L1.2 RV1.1 | length 1031.6
  Top Layer w10: 981.64,619.95 981.64,924.77 929.57,976.83 1178.57,976.83 1246,1044.26 1246,1353.07
NetJ4_2: J4.2 R86.1 | length 358.4
  Top Layer w20: R86.1@6276.5,1142 6276.5,941.94 J4.2@6388.44,830
NetJ4_3: J4.3 R85.2 | length 623.1
  Top Layer w20: R85.2@6252,1345.42 6268.58,1345.42 6318,1296 6318,1000.44 J4.3@6488.44,830
NetL5_14: L5.14 T1.1
NetQ2_1: Q2.1 Q3.1 R11.2 | length 2420.2
  Top Layer w20: v1(1716,2345.26) v1(1970,2599.26)
  Bottom Layer w20: v1(1716,2345.26) 1716,2055.26 1913,1858.26 2205,1858.26 2259,1912.26 2396,1912.26 2461.5,1977.76 R11.2@2461.5,2068.26 ; v1(1970,2599.26) 2206,2835.26 2206,2938.26 2264,2996.26 2264,3054.86 ; Q2.1@2163.6,3100.5 2163.6,3065.66 2174.4,3054.86 2264,3054.86 ; Q3.1@2317.6,3102.5 Q3.1@2317.6,3100.5 2317.6,3079.46 2293,3054.86 2264,3054.86
NetQ2_2: Q2.2 Q3.2 R9.1 R12.1
NetQ2_3: Q2.3 R13.2
NetQ4_1: Q4.1 Q5.3 R20.2
NetQ5_1: Q5.1 R21.1 R22.2 | length 256.9
  Bottom Layer w25: R21.1@2750.5,1869.26 2838.35,1869.26 Q5.1@2838.76,1868.86 2853.6,1868.86 2883,1898.26 2883,1989.76 R22.2@2868.5,2004.26
NetQ6_3: Q6.3 R22.1 | length 100.3
  Bottom Layer w25: R22.1@2931.5,2004.26 2931.5,2103.51 Q6.3@2932.24,2104.26
NetQ9_3: Q9.3 R55.1 | length 99.5
  Bottom Layer w30: R55.1@6172,1344.76 6175.74,1348.5 Q9.3@6270,1348.5
NetQ10_3: Q10.3 Q12.1 R71.1 | length 276.3
  Bottom Layer w25: R71.1@6629.5,641 6626.76,638.26 Q10.3@6626.76,525 6626.76,500.89 Q12.1@6722.24,405.4
NetQ12_3: Q12.3 R72.1 | length 115.5
  Bottom Layer w25: R72.1@6626.5,253 6627.76,254.26 Q12.3@6627.76,368
NetQ13_3: Q13.3 Q15.2 R83.1 R84.2 | length 233.4
  Bottom Layer w25: Q13.3@6778,703.76 6778,642.5 6776.5,641 6776.5,500 R84.2@6797,479.5
NetR1_1: R1.1 R2.2
NetR2_1: R2.1 R3.2
NetR6_2: R6.2 U1.4
NetR11_1: R11.1 U1.8 | length 88.9
  Bottom Layer w25: U1.8@2311.28,2072.26 2394.5,2072.26 R11.1@2398.5,2068.26
NetR14_1: R14.1 R15.2
NetR15_1: R15.1 R16.2
NetR24_1: R24.1 R25.2
NetR25_1: R25.1 R26.2
NetR36_1: R36.1 U4.4 | length 796.2
  Bottom Layer w25: R36.1@4602.5,1310.26 4670.5,1378.26 5130.15,1378.26 U4.4@5300.15,1208.26
NetR39_1: R39.1 U4.1 | length 110.8
  Top Layer w30: U4.1@5693.85,1208.26 5790.5,1208.26 R39.1@5800.5,1198.26
NetR40_1: R40.1 R41.1 U3.1 | length 216.2
  Top Layer w30: U3.1@5697.85,1456.26 5703.85,1462.26 R40.1@5801.5,1462.26
  Bottom Layer w30: U3.1@5697.85,1456.26 5719.35,1477.76 R41.1@5799,1477.76
NetR45_1: R45.1 R46.2 U6.5 | length 115.4
  Top Layer w20: v1(6399,1225.26) 6425,1199.26 U6.5@6425,1183.65
  Bottom Layer w30: R45.1@6368,1216.76 R46.2@6431,1216.76
NetR58_1: R58.1 R59.2 U6.2 | length 296.3
  Top Layer w20: v1(6487,1457.26) 6525,1419.26 U6.2@6525,1390.35
  Bottom Layer w25: R59.2@6368,1407.76 6448.5,1407.76 6487,1446.26 v1(6487,1457.26)
  Bottom Layer w30: R58.1@6300.5,1408.26 6301,1407.76 R59.2@6368,1407.76
NetR61_1: R61.1 U6.3 U8.1 | length 205.4
  Top Layer w20: v1(6438,1454.26) 6475,1417.26 U6.3@6475,1390.35
  Bottom Layer w25: v1(6438,1454.26) 6438,1490.76 R61.1@6434.5,1494.26 6434.5,1520.49 U8.1@6475.87,1561.86
NetR63_1: R63.1 R64.2 R87.2 | length 155.5
  Top Layer w15: R64.2@6055.5,1162.26 6055.5,1160.99 R87.2@6118.5,1098
  Top Layer w30: R63.1@5991,1160.76 6054,1160.76 R64.2@6055.5,1162.26
NetR77_1: R77.1 T2.3 U9.8
NetR78_2: R78.2 U9.4 | length 81.1
  Bottom Layer w20: R78.2@4307.5,813.26 4307.5,766.76 4323,751.26 U9.4@4335.72,751.26
PGND: C3.2 C4.2 C6.2 C7.2 C8.2 C9.2 C10.2 C12.2 C13.2 C14.2 C15.2 C16.2 C17.2 C18.2 C19.2 C20.2 C23.2 C25.2 C28.2 C30.2 C48.2 C49.2 C50.2 C58.2 D2.1 D2.2 H1.1 L4.7 Q1.3 Q3.3 Q4.3 Q6.2 Q8.3 R6.1 R7.2 R8.1 R17.1 R20.1 R23.1 R27.1 R34.1 R35.1 R38.1 R78.1 R80.1 RF1.2 T2.1 U1.1 U2.1 U2.11 U3.3 U4.3 U9.1 U9.2 U9.3 | length 2953.9
  Top Layer w10: Q1.3@2355,3641.26 2355,2665.05 RF1.2@3084.79,1935.26
  Top Layer w25: v1(4727,1542.26) 4773,1496.26 5244.15,1496.26 U3.3@5304.15,1556.26
  Bottom Layer w25: C12.2@2750.5,2105.26 2801.35,2105.26 Q6.2@2837.76,2141.66 ; C15.2@4357,2041.26 C17.2@4357,1953.26 4357,1930.26 4398,1889.26 U2.11@4398,1836.07
  other v1: 4610,1414.26 4162,1471.26 4220,1471.26 4162,1530.26 4220,1530.26 4083,1943 4152,1943 4083,2008 4153,2008 3050,2046.26 3125,2046.26 3200,2046.26 3050,2121.26 3125,2121.26 3200,2121.26 3050,2196.26 3125,2196.26 3200,2196.26
RVCC: C15.1 C17.1 R4.1 R32.1 R37.1 U2.12 | length 3271.5
  Top Layer w25: v1(2320,1296.26) 3580,1296.26 v1(4133,1849.26) 4157,1873.26 v1(4448,1873.26)
  Bottom Layer w25: R4.1@2316,1857.17 2316,1300.26 v1(2320,1296.26) ; v1(4133,1849.26) 4155,1871.26 R37.1@4166.5,1871.26 ; C17.1@4437,1953.26 4437,1944.26 4448,1933.26 v1(4448,1873.26) U2.12@4448,1836.07
  Bottom Layer w30: C17.1@4437,1953.26 C15.1@4437,2041.26 4439,2043.26 R32.1@4439,2130
SGND: C27.2 C29.2 C30.1 C35.2 C36.1 C39.2 C41.2 C43.2 C44.2 C47.2 C54.2 C55.2 C57.2 D14.2 D15.2 D18.2 D23.2 H2.1 J4.4 pad.1@5720,83 Q9.2 Q10.2 Q12.2 Q13.2 Q15.1 R44.1 R46.1 R52.1 R59.1 R62.1 R65.1 R67.2 R68.1 R69.1 R84.1 T1.9 T1.10 T2.6 U5.3 U6.4 U7.4 U8.2 | length 226.4
  Bottom Layer w20: U8.2@6475.87,1599.26 6497,1599.26 6518.5,1577.76 C47.2@6518.5,1496.26
  Bottom Layer w30: R67.2@6776.5,1639.26 6866.91,1639.26 R68.1@6869,1641.35
  other v1: 6140,684 6238,684 6388,684 6466,684 6553,684 6642,684 6914,782 6390,1000 6490,1000 6235,1085 5798,1091 6390,1094 6491,1094 5914,1165.26 6173,1262.26 6433,1337 6427,1592.26
VBIAS: C34.1 D16.1 R53.1 R62.2 R64.1 R65.2 R86.2 U7.2 | length 660.5
  Top Layer w20: v1(6022,1219) 6045,1219 ; U7.2@6045,1259.91 6045,1219 ; R64.1@6118.5,1162.26 6118.5,1165.76 6065.26,1219 6045,1219 ; D16.1@6204.31,1032 6204.31,1132.8 R86.2@6213.5,1142
  Top Layer w30: R64.1@6118.5,1162.26 6209.74,1162.26 6213,1159 R65.2@6213,1206.76 R62.2@6275,1206.76
  Bottom Layer w25: R53.1@5940.5,1284.26 5943.37,1281.39 5969.61,1281.39 6022,1229 v1(6022,1219)
  Bottom Layer w30: R53.1@5940.5,1284.26 5941,1284.76 C34.1@5941,1347.76
VBUS: C14.1 C22.1 C52.1 C58.1 Q7.2 R18.2 R24.2 R76.2 T2.5 | length 4160.1
  Bottom Layer w10: R18.2@3721.09,2900.26 3786,2965.17 3786,3177.41 3855.85,3247.26 3997.15,3247.26 4002.15,3242.26
  Bottom Layer w60: R18.2@3698.09,2914.26 3927.91,2684.43 R24.2@3927.91,1301.26 3927.91,649.09 4136.74,440.26 T2.5@5090,440.26
VCC: C13.1 R74.1 U2.3 | length 310.3
  Bottom Layer w25: U2.3@4548,1623.47 4548,1597.26 4576,1569.26 4620,1569.26 C13.1@4665,1524.26 4676.09,1524.26 R74.1@4765,1435.35
VCC_PFC: C3.1 C10.1 Q5.2 R4.2 R13.1 R19.2 R21.2 U1.7 | length 2543.6
  Top Layer w25: v1(1751,2318.26) v1(2002,2569.26) ; v1(2382,1967.26) 2443,1906.26 v1(2710,1906.26)
  Bottom Layer w25: v1(1751,2318.26) 1751,2082.26 1925,1908.26 2177,1908.26 2222,1953.26 C3.1@2222,1978.26 ; v1(2002,2569.26) 2260,2827.26 2260,2896.17 R13.1@2267.09,2903.26 ; U1.7@2311.28,2122.26 2272,2122.26 2222,2072.26 C3.1@2222,1978.26 ; v1(2382,1967.26) 2320.09,1967.26 R4.2@2316,1971.35 2228.91,1971.35 C3.1@2222,1978.26 ; R21.2@2687.5,1869.26 2687.5,1883.76 v1(2710,1906.26) 2751.5,1947.76 R19.2@2751.5,1952.26 2760.09,1943.66 Q5.2@2838.76,1943.66
VCR: C24.2 C25.1 U2.7 | length 667.8
  Top Layer w25: v1(4305,1554) 4466,1715 4740.65,1715 C24.2@4763.91,1738.26
  Bottom Layer w25: C25.1@4276,1520.76 4276,1525.95 4348,1597.95 U2.7@4348,1623.47
VOUT: C37.1 C38.1 C39.1 C41.1 C44.1 C46.1 D11.2 D12.2 J2.2 R43.2 R63.2 | length 4273.5
  Top Layer w25: v1(5989,1062.26) 5989,907 6148,748 6766.74,748 6880.32,861.58 6924.68,905.94 J2.2@7279,1260.26
  Top Layer w30: v1(5989,1062.26) 5989,1095.76 R63.2@5991,1097.76
  Bottom Layer w10: D12.2@6275,3461.26 6275,3343.26 6382,3236.26 6911,3236.26 ; D11.2@6908,3459.26 6908,3239.26 6911,3236.26 ; C39.1@7184.64,1951.26 C41.1@7184.64,2819.26 7184.64,2962.62 6911,3236.26
  Bottom Layer w25: J2.2@7279,1260.26 7324.74,1260.26
  Bottom Layer w30: v1(5989,1062.26) 6011.5,1062.26 R43.2@6029,1079.76
VREF: R45.2 R56.2 R57.2 U7.3 | length 632.4
  Top Layer w20: R56.2@5866,1334.76 5882.5,1351.26 6047,1351.26 v1(6096,1302.26) 6095,1301.26 U7.3@6095,1259.91
  Bottom Layer w20: v1(6096,1302.26) 6345.5,1302.26 R45.2@6368,1279.76
  Bottom Layer w25: v1(6096,1302.26) 6096,1323.76 6113,1340.76 R57.2@6109,1344.76
VS: R79.1 R80.2 U9.5 | length 183.7
  Bottom Layer w20: U9.5@4550.28,751.26 R79.1@4635.5,751.26 4635.5,760.27 4661.92,786.69 4662.59,786.69 4698.5,822.59 R80.2@4698.5,823.26
pads on no net: L4.12 L5.6 L5.7 T1.6 T2.4 T2.8 T2.9

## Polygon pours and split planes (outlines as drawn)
SGND on Top Layer "Top Layer-No Net 21" (solid, remove dead copper, pour order 212): 6956.84,2958.36 6789.84,2958.36 6688.84,2857.36 6688.84,2700.36 6616.84,2628.36 6410.84,2628.36 6374.84,2592.36 6374.84,2233.36 6472.84,2135.36 6579.84,2135.36 6625.84,2089.36 6625.84,1786.36 6549.84,1710.36 5808.84,1710.36 5684.84,1586.36 5685.84,1585.36 5685.84,510.36 5671.84,496.36 5671.84,69.1 5710.84,30.1 7099.58,30.1 7462.84,393.36 7462.84,826.36 7357.84,931.36 7184.84,931.36 7041.84,1074.36 7041.84,2873.36
NetD1_2 on Top Layer "Bottom Layer-No Net 13" (solid, pour order 198): 414.26,3431.26 575,3431.26 700,3556.26 793.74,3650 947,3650 987,3610 987,3546.26 872,3431.26 751,3431.26 445,3125.26 357,3125.26 356,3124.26 323,3124.26 271,3176.26 271,3288
NetD1_3 on Top Layer "Bottom Layer-No Net 12" (solid, remove dead copper, pour order 196): 920,3327.26 1111,3518.26 1111,3609 1152,3650 1277,3650 1317,3610 1317,3458.26 984,3125.26 764,3125.26 728,3161.26 728,3195.26 728,3259.26 796,3327.26
"L Wire" on Top Layer "Top Layer-No Net" (solid, remove dead copper, pour order 190): 918.5,415 984.5,481 1253.5,481 1290.5,444 1290.5,346 1265.5,321 932.5,321 918.5,335
VOUT on Top Layer "Top Layer-No Net 20" (solid, remove dead copper, pour order 156): 7142,3014.26 7343,3014.26 7417,2940.26 7417,1239.26 7371,1193.26 7214,1193.26 7077,1330.26 7077,2949.26
PGND on Top Layer "Top Layer-No Net 14" (solid, pour order 118): 2340,3697.26 2319,3697.26 2288,3666.26 2288,3530.26 2222,3464.26 2116,3464.26 2076,3424.26 2076,2845.26 1940,2709.26 1710,2709.26 1493,2492.26 1493,1597.26 1679,1411.26 3047,1411.26 3382,1746.26 3382,2779.26 3514,2911.26 3514,2915.26 3312,3117.26 3004,2809.26 2581,2809.26 2481,2909.26 2482,2910.26 2482,3667.26 2452,3697.26
PGND on Top Layer "Top Layer-No Net 13" (solid, pour order 112): 4285,3585 4314,3556 4314,3376.26 4355,3335.26 4532,3335.26 4583,3284.26 4583,3195.26 4539,3151.26 4394.05,3151.26 4341,3098.21 4341,2900.26 4273,2832.26 4101,2832.26 4011,2922.26 4011,3109.26 3969,3151.26 3806,3151.26 3747,3210.26 3747,3249.26 3636,3360.26 3382,3360.26 3234,3212.26 3234,3036 3358.74,2911.26 3646,2911.26 3701,2856.26 3701,2771.26 3701,2138.26 3923,1916.26 4460,1916.26 4484,1940.26 4484,2087 4318,2253 4318,2351 4388,2421 4472,2421 4717,2176 4717,1965.26 4747,1965.26 4895,1965.26 4923,1993.26 4923,3016.26 5058,3151.26 5307,3151.26 5345,3189.26 5345,3319.26 5299,3365.26 5098,3365.26 4695,3768.26 4487,3768.26 4377,3658.26 4302,3658.26 4285,3641.26
HS on Top Layer "Top Layer-No Net 12" (solid, pour order 80): 4203,3551 4246,3551 4263,3534 4263,2909.26 4238,2884.26 4151,2884.26 4086,2949.26 4086,3315.57 4038.31,3363.26 3855.74,3363.26 3623,3596 3623,3642.26 3655.74,3675 3728.26,3675 3880.26,3523 4175,3523
NetD5_2 on Top Layer "Top Layer-No Net 11" (solid, remove dead copper, pour order 72): 2076,3823.26 2159.74,3907 2947.26,3907 3089,3765.26 3089,3033.26 2952,2896.26 2599,2896.26 2553,2942.26 2553,3055.26 2620,3122.26 2808,3122.26 2872,3186.26 2872,3674.26 2805,3741.26 2253,3741.26 2215,3703.26 2215,3592.26 2181,3558.26 2111,3558.26 2076,3593.26
NetC5_2 on Top Layer "Top Layer-No Net 10" (solid, pour order 70): 1462,3684.26 1430,3652.26 1430,3431.26 1318,3319.26 1318,3270.26 1351,3237.26 1453,3237.26 1560,3344.26 1560,3666.26 1542,3684.26
NetC5_1 on Top Layer "Top Layer-No Net 9" (solid, pour order 68): 422,3730 597,3905 1711.26,3905 1774,3842.26 1774,3517.26 1908,3383.26 1963,3383.26 2016,3330.26 2016,2938.26 1957,2879.26 1658,2879.26 1449,2670.26 1310,2670.26 1273,2707.26 1273,2857.26 1551,3135.26 1647,3231.26 1647,3397.26 1647,3418.26 1647,3713.26 1611,3749.26 754.26,3749.26 536.39,3531.39 458.87,3531.39 422,3568.26
NetD12_1 on Top Layer "Top Layer-No Net 8" (solid, pour order 36): 6113,3525.26 6204,3525.26 6216,3513.26 6216,3401.26 6241,3376.26 6309,3376.26 6334,3401.26 6334,3513.26 6346,3525.26 6405,3525.26 6439,3491.26 6439,3150.26 6345,3056.26 6345,2204.26 6446,2103.26 6532,2103.26 6593,2042.26 6593,1829.26 6531,1767.26 6357,1767.26 6070,2054.26 6070,3482.26
NetD11_1 on Top Layer "Top Layer-No Net 7" (solid, remove dead copper, pour order 34): 6419,3014.26 6733,3328.26 6733,3490.26 6767,3524.26 6836,3524.26 6849,3511.26 6849,3388.26 6863,3374.26 6953,3374.26 6967,3388.26 6967,3511.26 6980,3524.26 7034,3524.26 7068,3490.26 7068,3297.26 6650,2879.26 6650,2718.26 6593,2661.26 6485,2661.26 6419,2727.26
EARTH on Top Layer "Bottom Layer-No Net 4" (solid, pour order 32): 22,1330.26 116,1330.26 133,1313.26 133,650 331.74,451.26 485.74,451.26 510,427 510,228 610,128 1268,128 1297,99 1297,37 1276,16 469,16 362,123 362,233 244,351 104.26,351 4,451.26 4,1312.26
NetC2_2 on Top Layer "Top Layer-No Net 6" (solid, remove dead copper, pour order 16): 730,2833.26 879,2833.26 1022,2690.26 1022,2386.26 974,2338.26 974,2119.26 944,2089.26 805,2089.26 779,2115.26 779,2556.26 708,2627.26 708,2811.26
NetC2_1 on Top Layer "Top Layer-No Net 5" (solid, remove dead copper, pour order 14): 466,2833.26 483,2816.26 483,2542.26 526,2499.26 526,2115.26 501,2090.26 341,2090.26 316,2115.26 316,2388.26 283,2421.26 283,2814.26 302,2833.26
NetC1_1 on Top Layer "Top Layer-No Net 4" (solid, pour order 12): 947,1893.26 974,1866.26 974,1700.26 1044,1630.26 1044,1182 997,1135 886,1135 838,1183 838,1590.26 780,1648.26 780,1864.26 809,1893.26
NetC1_2 on Top Layer "Top Layer-No Net 3" (solid, pour order 10): 500,1893.26 524,1869.26 524,1701.26 726,1499.26 726,1184 677,1135 571.74,1135 433,996.26 433,909.26 401,877.26 330,877.26 299,908.26 299,979.26 554,1234.26 554,1421.26 484,1491.26 331,1491.26 286,1536.26 286,1869.26 310,1893.26
"N Wire" on Top Layer "Top Layer-No Net 2" (solid, pour order 8): 673,321 645,349 645,605.26 539,711.26 539,1001.26 595.74,1058 683,1058 724,1017 724,899.26 802,821.26 802,349 774,321
NetF1_1 on Top Layer "Top Layer-No Net 1" (solid, remove dead copper, pour order 2): 858.5,932.5 913.5,877.5 913.5,620.5 946.5,587.5 1037.5,587.5 1068.5,618.5 1068.5,826.5 1161.5,919.5 1293.5,1051.5 1293.5,1411.5 1264,1441 1174,1441 1142.5,1409.5 1142.5,1144.24 1067.5,1069.24 898.5,1069.24 858.5,1029.24
"L Wire" on Top Layer "Top Layer-No Net" (solid, remove dead copper, pour order 0): 918.5,415 984.5,481 1253.5,481 1290.5,444 1290.5,346 1265.5,321 932.5,321 918.5,335
NetR77_1 on Top Layer "Top Layer-No Net 15" (solid, pour order 132): 4880,577.26 4953,577.26 5064,688.26 5105,688.26 5120,673.26 5120,630.26 5111,621.26 5069,621.26 4971,523.26 4880,523.26 4877,526.26 4877,574.26
NetD21_2 on Top Layer "Top Layer-No Net 16" (solid, pour order 134): 4782,696.26 4949,696.26 4955,690.26 4955,639.26 4950,634.26 4873,634.26 4860,621.26 4856,617.26 4785,617.26 4782,620.26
